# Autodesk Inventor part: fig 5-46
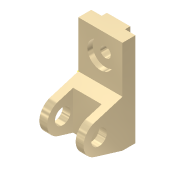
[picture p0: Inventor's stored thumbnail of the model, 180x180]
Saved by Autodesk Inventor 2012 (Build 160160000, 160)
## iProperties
Shininess: 65.0
Angle Display Precision: 2
Document Length Units: 11269
Document Angle Units: 11279
Document Time Units: 11290
Document Mass Units: 11283
Document Length Units Precision: 3
Document Angle Units Precision: 2
Created: 2001-11
Part Number: fig 5-46
Document SubType Name: Modeling
Designer: Renu Muthoo
Density: 1 g/cm^3
Material: Default
Density: 0.0
Volumn: 0.0
Area: 0.0
PropertySet Name: Model Information
Control State: 0
Master: False
Checked Out: False
Author: Renu Muthoo
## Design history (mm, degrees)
node "Sketch1"
sketch "Sketch2"
  geometry: L1 (33.257, 104.664)-(33.257, -75.336); L2 (33.257, -75.336)-(8.257, -75.336); L3 (8.257, -75.336)-(-45.451, -59.045); L4 (-45.451, -1.628)-(8.257, 14.664); L5 (8.257, 14.664)-(8.257, 104.664); L6 (8.257, 104.664)-(33.257, 104.664); C1 r 15 at (-36.743, -30.336); A1 r 30 centre (-36.743, -30.336) between (-45.451, -1.628) and (-45.451, -59.045)
  constraints: 12 end point, 2 centre point, 2 equal length, 2 parallel, 2 point on circle, 2 tangent, 1 coincident, 1 perpendicular, 1 vertical
  dimensions: "d0" = 180 distance of L1.start L1.end; "d1" = 30 radius of A1; "d2" = 25 distance of L5.end L1.start; "d3" = 45 distance from line of L2 A1.centre; "d4" = 70 distance from line of L1 A1.centre; "d5" = 30 diameter of C1
extrude "Extrusion1" new body sketch "Sketch2" distance "d6" = 85; taper "d7" = 0 deg
workplane "Work Plane1"
sketch "Sketch3"
  geometry: L1 (15, 62.364)-(70, 62.364); L2 (70, 62.364)-(70, -52.386); L3 (70, -52.386)-(15, -52.386); L4 (15, -52.386)-(15, 62.364); L5 (0, -45)-(0, -28.708) reference
  constraints: 8 end point, 2 parallel, 1 horizontal, 1 perpendicular
  dimensions: "d8" = 55 distance of L1.start L1.end; "d9" = 15 distance between parallel lines of L5 L4
extrude "Extrusion2" cut sketch "Sketch3" distance "d10" = 50; taper "d11" = 0 deg
sketch "Sketch4"
  geometry: L1 (0, 25)-(85, 25) reference; L2 (0, 0)-(0, 25) reference; L3 (20, 25)-(65, 25); L4 (65, 25)-(65, 35); L5 (65, 35)-(20, 35); L6 (20, 35)-(20, 25)
  constraints: 8 end point, 2 parallel, 1 horizontal, 1 perpendicular, 1 point on line
  dimensions: "d12" = 45 distance of L4.end L5.end; "d13" = 10 distance of L3.end L4.end; "d14" = 20 distance between parallel lines of L2 L6
extrude "Extrusion3" join sketch "Sketch4" stored distance "d15" = 50; taper "d16" = 0 deg
sketch "Sketch5"
  geometry: L1 (85, 0)-(85, 90) reference; L2 (0, 90)-(85, 90) reference; 1 further point
  dimensions: "d17" = 42 distance from line of L2 point (42.5, 48); "d18" = 42.5 distance from line of L1 point (42.5, 48)
hole "Hole1" sketch "Sketch5" at (42.5, 48) diameter "d19" = 20; stored, may be unused: countersink angle "d23" = 82 deg, drill point angle "d25" = 118 deg; dims "d20" = 6, "d21" = 50, "d22" = 10, "d24" = 8
workpoint "Work Point5"
body "Solid1"
